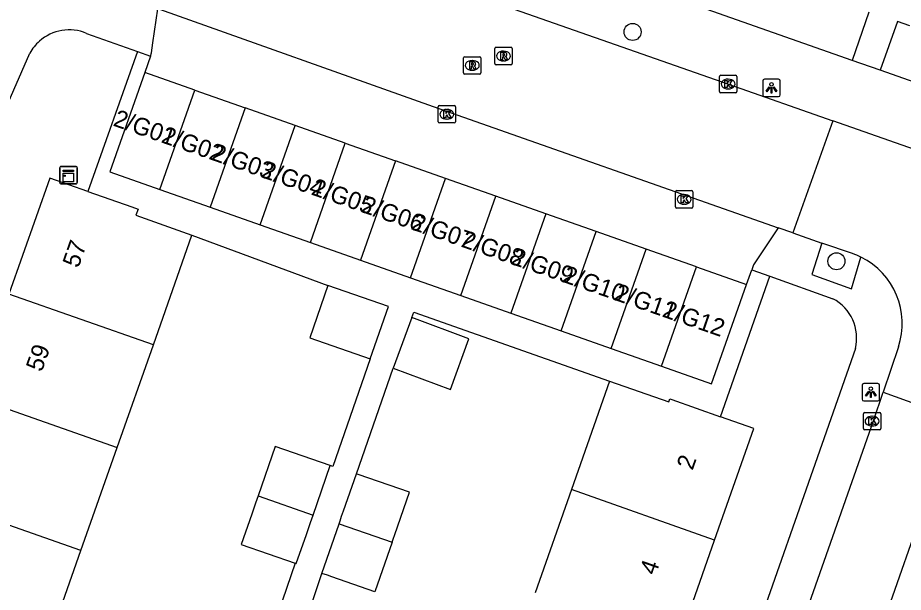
# Model space of a CAD drawing. Extents: x 163268 to 164360, y 381529 to 382285.
# Drawn here: x 163679.2 to 163730.1, y 381780.9 to 381813.9 of the extents above; entities that cross this region are included whole.
import ezdxf

# ---------------------------------------------------------------- set-up
doc = ezdxf.new("R2010")
doc.units = 0
for name, color, linetype in [('IMGEO_Boom', 7, 'Continuous'), ('IMGEO_Kast', 7, 'Continuous'), ('IMGEO_Kolk', 7, 'Continuous'), ('IMGEO_Lichtpunt', 7, 'Continuous'), ('IMGEO_Pand', 7, 'Continuous'), ('IMGEO_Pand_nummerreeks', 7, 'Continuous'), ('IMGEO_Rijbaan_lokaal_open', 7, 'Continuous'), ('IMGEO_Rioolput', 7, 'Continuous'), ('IMGEO_Voetpad_open', 7, 'Continuous')]:
    doc.layers.add(name, color=color, linetype=linetype)

msp = doc.modelspace()

# ---------------------------------------------------------------- linework, layer by layer
at = {"layer": 'IMGEO_Boom'}
for centre in [(163714.53, 381813.112), (163726.256, 381799.927)]:
    msp.add_circle(centre, 0.489, dxfattribs=at)
at = {"layer": 'IMGEO_Kast'}
for p, q in [((163681.652, 381805.379), (163682.493, 381805.379)), ((163682.493, 381805.379), (163681.652, 381805.379)), ((163681.577, 381804.454), (163681.577, 381805.295)), ((163681.577, 381805.295), (163681.577, 381804.454)), ((163682.577, 381805.304), (163682.577, 381804.463)), ((163682.577, 381804.463), (163682.577, 381805.304)), ((163682.502, 381804.379), (163681.661, 381804.379)), ((163681.661, 381804.379), (163682.502, 381804.379))]:
    msp.add_line(p, q, dxfattribs=at)
for points in [[(163681.772, 381805.169), (163682.372, 381805.169), (163682.372, 381805.084), (163681.772, 381805.084), (163681.772, 381805.169)], [(163681.772, 381804.994), (163682.372, 381804.994), (163682.372, 381804.505), (163681.772, 381804.505), (163681.772, 381804.994)]]:
    msp.add_lwpolyline(points, dxfattribs=at)
msp.add_circle((163681.856, 381804.843), 0.0377, dxfattribs=at)
for centre, start, end in [((163681.655, 381805.301), 92.4484, 184.2845), ((163681.655, 381805.301), 92.4484, 184.2845), ((163682.499, 381805.301), 2.4484, 94.2845), ((163682.499, 381805.301), 2.4484, 94.2845), ((163681.655, 381804.457), 182.4484, 274.2845), ((163681.655, 381804.457), 182.4484, 274.2845), ((163682.499, 381804.457), 272.4484, 4.2845), ((163682.499, 381804.457), 272.4484, 4.2845)]:
    msp.add_arc(centre, 0.0779, start, end, dxfattribs=at)
at = {"layer": 'IMGEO_Kolk'}
for p, q in [((163719.522, 381809.693), (163719.522, 381810.545)), ((163719.597, 381810.619), (163720.449, 381810.619)), ((163720.523, 381810.545), (163720.523, 381809.693)), ((163720.01, 381810.399), (163720.035, 381810.399)), ((163720.449, 381809.619), (163719.597, 381809.619)), ((163720.033, 381809.839), (163720.008, 381809.839)), ((163703.341, 381807.953), (163703.341, 381808.805)), ((163703.416, 381808.879), (163704.268, 381808.879)), ((163703.829, 381808.659), (163703.854, 381808.659)), ((163704.342, 381808.805), (163704.342, 381807.953)), ((163703.852, 381808.099), (163703.827, 381808.099)), ((163704.268, 381807.879), (163703.416, 381807.879)), ((163716.996, 381803.062), (163716.996, 381803.914)), ((163717.071, 381803.988), (163717.923, 381803.988)), ((163717.997, 381803.914), (163717.997, 381803.062)), ((163717.484, 381803.768), (163717.509, 381803.768)), ((163717.923, 381802.988), (163717.071, 381802.988)), ((163717.507, 381803.208), (163717.482, 381803.208)), ((163727.803, 381790.312), (163727.803, 381791.164)), ((163727.878, 381791.238), (163728.73, 381791.238)), ((163728.804, 381791.164), (163728.804, 381790.312)), ((163728.291, 381791.018), (163728.316, 381791.018)), ((163728.73, 381790.238), (163727.878, 381790.238)), ((163728.314, 381790.458), (163728.289, 381790.458))]:
    msp.add_line(p, q, dxfattribs=at)
for points in [[(163719.522, 381809.693), (163719.522, 381810.545)], [(163719.597, 381810.619), (163720.449, 381810.619)], [(163720.523, 381810.545), (163720.523, 381809.693)], [(163719.843, 381810.319), (163719.966, 381810.319), (163719.966, 381810.168), (163720.096, 381810.319), (163720.26, 381810.319), (163720.114, 381810.168), (163720.267, 381809.919), (163720.115, 381809.919), (163720.03, 381810.083), (163719.966, 381810.016), (163719.966, 381809.919), (163719.843, 381809.919), (163719.843, 381810.319)], [(163720.449, 381809.619), (163719.597, 381809.619)], [(163703.341, 381807.953), (163703.341, 381808.805)], [(163703.416, 381808.879), (163704.268, 381808.879)], [(163703.662, 381808.579), (163703.785, 381808.579), (163703.785, 381808.428), (163703.915, 381808.579), (163704.079, 381808.579), (163703.933, 381808.428), (163704.086, 381808.179), (163703.934, 381808.179), (163703.849, 381808.343), (163703.785, 381808.276), (163703.785, 381808.179), (163703.662, 381808.179), (163703.662, 381808.579)], [(163704.342, 381808.805), (163704.342, 381807.953)], [(163704.268, 381807.879), (163703.416, 381807.879)], [(163716.996, 381803.062), (163716.996, 381803.914)], [(163717.071, 381803.988), (163717.923, 381803.988)], [(163717.997, 381803.914), (163717.997, 381803.062)], [(163717.317, 381803.688), (163717.44, 381803.688), (163717.44, 381803.537), (163717.57, 381803.688), (163717.734, 381803.688), (163717.588, 381803.537), (163717.741, 381803.288), (163717.589, 381803.288), (163717.504, 381803.452), (163717.44, 381803.385), (163717.44, 381803.288), (163717.317, 381803.288), (163717.317, 381803.688)], [(163717.923, 381802.988), (163717.071, 381802.988)], [(163727.803, 381790.312), (163727.803, 381791.164)], [(163727.878, 381791.238), (163728.73, 381791.238)], [(163728.804, 381791.164), (163728.804, 381790.312)], [(163728.124, 381790.938), (163728.247, 381790.938), (163728.247, 381790.787), (163728.377, 381790.938), (163728.541, 381790.938), (163728.395, 381790.787), (163728.548, 381790.538), (163728.396, 381790.538), (163728.311, 381790.702), (163728.247, 381790.635), (163728.247, 381790.538), (163728.124, 381790.538), (163728.124, 381790.938)], [(163728.73, 381790.238), (163727.878, 381790.238)]]:
    msp.add_lwpolyline(points, dxfattribs=at)
for centre, start, end in [((163719.599, 381810.543), 91.552, 178.448), ((163719.599, 381810.543), 91.552, 178.448), ((163720.447, 381810.543), 1.552, 88.448), ((163720.447, 381810.543), 1.552, 88.448), ((163719.599, 381809.695), 181.552, 268.448), ((163719.599, 381809.695), 181.552, 268.448), ((163720.447, 381809.695), 271.552, 358.448), ((163720.447, 381809.695), 271.552, 358.448), ((163703.418, 381808.803), 91.552, 178.448), ((163703.418, 381808.803), 91.552, 178.448), ((163704.266, 381808.803), 1.552, 88.448), ((163704.266, 381808.803), 1.552, 88.448), ((163703.418, 381807.955), 181.552, 268.448), ((163703.418, 381807.955), 181.552, 268.448), ((163704.266, 381807.955), 271.552, 358.448), ((163704.266, 381807.955), 271.552, 358.448), ((163717.073, 381803.912), 91.552, 178.448), ((163717.073, 381803.912), 91.552, 178.448), ((163717.921, 381803.912), 1.552, 88.448), ((163717.921, 381803.912), 1.552, 88.448), ((163717.073, 381803.064), 181.552, 268.448), ((163717.073, 381803.064), 181.552, 268.448), ((163717.921, 381803.064), 271.552, 358.448), ((163717.921, 381803.064), 271.552, 358.448), ((163727.88, 381791.162), 91.552, 178.448), ((163727.88, 381791.162), 91.552, 178.448), ((163728.728, 381791.162), 1.552, 88.448), ((163728.728, 381791.162), 1.552, 88.448), ((163727.88, 381790.314), 181.552, 268.448), ((163727.88, 381790.314), 181.552, 268.448), ((163728.728, 381790.314), 271.552, 358.448), ((163728.728, 381790.314), 271.552, 358.448)]:
    msp.add_arc(centre, 0.0765, start, end, dxfattribs=at)
for centre, major_axis, ratio, start_param, end_param in [((163720.009, 381810.119), (-0.387, 0.002), 0.722429, 4.712389, 7.853982), ((163720.034, 381810.119), (-0.39, 0.002), 0.717154, 1.570796, 4.712389), ((163703.828, 381808.379), (-0.387, 0.002), 0.722429, 4.712389, 7.853982), ((163703.853, 381808.379), (-0.39, 0.002), 0.717154, 1.570796, 4.712389), ((163717.483, 381803.488), (-0.387, 0.002), 0.722429, 4.712389, 7.853982), ((163717.508, 381803.488), (-0.39, 0.002), 0.717154, 1.570796, 4.712389), ((163728.29, 381790.738), (-0.387, 0.002), 0.722429, 4.712389, 7.853982), ((163728.315, 381790.738), (-0.39, 0.002), 0.717154, 1.570796, 4.712389)]:
    msp.add_ellipse(centre, major_axis=major_axis, ratio=ratio, start_param=start_param, end_param=end_param, dxfattribs=at)
at = {"layer": 'IMGEO_Lichtpunt'}
for p, q in [((163722.02, 381810.301), (163722.02, 381809.494)), ((163722.02, 381810.301), (163722.02, 381809.494)), ((163722.922, 381810.396), (163722.114, 381810.396)), ((163722.922, 381810.396), (163722.114, 381810.396)), ((163723.016, 381809.494), (163723.016, 381810.301)), ((163723.016, 381809.494), (163723.016, 381810.301)), ((163722.114, 381809.4), (163722.922, 381809.4)), ((163722.114, 381809.4), (163722.922, 381809.4)), ((163727.735, 381792.805), (163727.735, 381791.998)), ((163727.735, 381792.805), (163727.735, 381791.998)), ((163728.637, 381792.9), (163727.829, 381792.9)), ((163728.637, 381792.9), (163727.829, 381792.9)), ((163728.731, 381791.998), (163728.731, 381792.805)), ((163728.731, 381791.998), (163728.731, 381792.805)), ((163727.829, 381791.904), (163728.637, 381791.904)), ((163727.829, 381791.904), (163728.637, 381791.904))]:
    msp.add_line(p, q, dxfattribs=at)
for points in [[(163722.394, 381809.965), (163722.433, 381809.937), (163722.245, 381809.675), (163722.207, 381809.702), (163722.394, 381809.965)], [(163722.606, 381809.937), (163722.644, 381809.964), (163722.831, 381809.702), (163722.792, 381809.674), (163722.606, 381809.937)], [(163722.496, 381809.917), (163722.543, 381809.917), (163722.543, 381809.595), (163722.496, 381809.595), (163722.496, 381809.917)], [(163728.109, 381792.469), (163728.148, 381792.441), (163727.96, 381792.179), (163727.922, 381792.206), (163728.109, 381792.469)], [(163728.211, 381792.421), (163728.258, 381792.421), (163728.258, 381792.099), (163728.211, 381792.099), (163728.211, 381792.421)], [(163728.321, 381792.441), (163728.359, 381792.468), (163728.546, 381792.206), (163728.507, 381792.178), (163728.321, 381792.441)]]:
    msp.add_lwpolyline(points, dxfattribs=at)
for centre in [(163722.519, 381810.099), (163728.234, 381792.603)]:
    msp.add_circle(centre, 0.0994, dxfattribs=at)
for centre, start, end in [((163722.114, 381810.301), 90, 180), ((163722.114, 381810.301), 90, 180), ((163722.922, 381810.301), 0, 90), ((163722.922, 381810.301), 0, 90), ((163722.114, 381809.494), 180, 270), ((163722.114, 381809.494), 180, 270), ((163722.922, 381809.494), 270, 0), ((163722.922, 381809.494), 270, 360), ((163727.829, 381792.805), 90, 180), ((163727.829, 381792.805), 90, 180), ((163728.637, 381792.805), 0, 90), ((163728.637, 381792.805), 0, 90), ((163727.829, 381791.998), 180, 270), ((163727.829, 381791.998), 180, 270), ((163728.637, 381791.998), 270, 0), ((163728.637, 381791.998), 270, 360)]:
    msp.add_arc(centre, 0.0946, start, end, dxfattribs=at)
at = {"layer": 'IMGEO_Pand'}
for points in [[(163686.459, 381810.779), (163684.448, 381805.066), (163687.333, 381804.05)], [(163689.345, 381809.763), (163686.459, 381810.779)], [(163687.333, 381804.05), (163689.345, 381809.763)], [(163689.345, 381809.763), (163692.23, 381808.748)], [(163692.23, 381808.748), (163690.219, 381803.034)], [(163695.115, 381807.732), (163692.23, 381808.748)], [(163693.104, 381802.019), (163695.115, 381807.732)], [(163698, 381806.716), (163695.115, 381807.732)], [(163695.989, 381801.003), (163698, 381806.716)], [(163698, 381806.716), (163700.886, 381805.701)], [(163700.886, 381805.701), (163698.874, 381799.987)], [(163703.771, 381804.685), (163700.886, 381805.701)], [(163683.186, 381803.942), (163681.001, 381804.712), (163678.652, 381798.043)], [(163701.76, 381798.972), (163703.771, 381804.685)], [(163706.656, 381803.669), (163703.771, 381804.685)], [(163683.186, 381803.942), (163685.717, 381803.051), (163686.08, 381802.923), (163685.957, 381802.573), (163689.18, 381801.438)], [(163687.333, 381804.05), (163690.219, 381803.034)], [(163704.645, 381797.956), (163706.656, 381803.669)], [(163709.541, 381802.654), (163706.656, 381803.669)], [(163690.219, 381803.034), (163693.104, 381802.019)], [(163709.541, 381802.654), (163707.53, 381796.94)], [(163712.427, 381801.638), (163709.541, 381802.654)], [(163693.104, 381802.019), (163695.989, 381801.003)], [(163686.959, 381795.132), (163689.18, 381801.438)], [(163710.415, 381795.924), (163712.427, 381801.638)], [(163715.312, 381800.622), (163712.427, 381801.638)], [(163695.989, 381801.003), (163698.874, 381799.987)], [(163713.3, 381794.908), (163715.312, 381800.622)], [(163718.197, 381799.606), (163715.312, 381800.622)], [(163698.874, 381799.987), (163701.76, 381798.972)], [(163716.186, 381793.893), (163718.197, 381799.606)], [(163718.197, 381799.606), (163721.082, 381798.591)], [(163701.76, 381798.972), (163704.645, 381797.956)], [(163697.003, 381798.534), (163695.961, 381795.52), (163699.434, 381794.32)], [(163699.434, 381794.32), (163700.476, 381797.334), (163697.003, 381798.534)], [(163716.186, 381793.893), (163719.071, 381792.877), (163721.082, 381798.591)], [(163686.959, 381795.132), (163678.652, 381798.043)], [(163704.645, 381797.956), (163707.53, 381796.94)], [(163707.53, 381796.94), (163710.415, 381795.924)], [(163701.825, 381796.689), (163700.753, 381793.774)], [(163700.753, 381793.774), (163704.043, 381792.564), (163705.115, 381795.479), (163701.825, 381796.689)], [(163710.415, 381795.924), (163713.3, 381794.908)], [(163684.876, 381789.218), (163686.959, 381795.132)], [(163713.3, 381794.908), (163716.186, 381793.893)], [(163713.208, 381793.042), (163711.009, 381786.801)], [(163713.208, 381793.042), (163716.608, 381791.845), (163716.668, 381792.016), (163716.791, 381791.973), (163719.576, 381790.993)], [(163676.569, 381792.13), (163684.876, 381789.218)], [(163719.249, 381783.902), (163721.507, 381790.314), (163719.576, 381790.993)], [(163682.793, 381783.305), (163684.876, 381789.218)], [(163697.139, 381788.189), (163693.974, 381789.288), (163692.983, 381786.435)], [(163696.148, 381785.337), (163697.139, 381788.189)], [(163697.64, 381784.841), (163697.698, 381785.01), (163697.788, 381785.267), (163697.899, 381785.587), (163698.637, 381787.711)], [(163700.691, 381783.782), (163700.75, 381783.951), (163700.841, 381784.213), (163701.688, 381786.651), (163698.736, 381787.677), (163698.637, 381787.711)], [(163711.009, 381786.801), (163708.919, 381780.869)], [(163719.249, 381783.902), (163711.009, 381786.801)], [(163682.793, 381783.305), (163674.486, 381786.216)], [(163692.983, 381786.435), (163692.838, 381786.018), (163692.619, 381785.386), (163692.014, 381783.644), (163695.11, 381782.57)], [(163692.983, 381786.435), (163696.148, 381785.337)], [(163695.11, 381782.57), (163695.179, 381782.546), (163695.761, 381784.222), (163696.003, 381784.919), (163696.148, 381785.337)], [(163696.648, 381781.987), (163697.64, 381784.841)], [(163697.64, 381784.841), (163700.691, 381783.782)], [(163700.691, 381783.782), (163699.7, 381780.928), (163697.218, 381781.79), (163696.979, 381781.873), (163696.648, 381781.987)], [(163717.161, 381777.97), (163719.249, 381783.902)], [(163680.71, 381777.391), (163682.793, 381783.305)]]:
    msp.add_lwpolyline(points, dxfattribs=at)
at = {"layer": 'IMGEO_Rijbaan_lokaal_open'}
for points in [[(163685.076, 381822.394), (163704.639, 381815.509), (163720.044, 381810.112), (163726.041, 381807.998)], [(163687.218, 381814.444), (163687.304, 381814.414), (163703.06, 381808.819), (163722.904, 381801.849)], [(163726.041, 381807.998), (163723.746, 381801.558)], [(163758.246, 381796.703), (163740.853, 381802.813), (163726.041, 381807.998)], [(163723.746, 381801.558), (163722.904, 381801.849)], [(163723.746, 381801.558), (163725.421, 381800.978)], [(163727.182, 381800.368), (163725.421, 381800.978)], [(163729.821, 381795.001), (163728.949, 381792.401)], [(163708.144, 381732.996), (163708.709, 381734.601), (163714.691, 381751.607), (163721.738, 381771.833), (163728.396, 381790.753), (163728.949, 381792.401)], [(163728.949, 381792.401), (163733.076, 381790.916)], [(163733.076, 381790.916), (163732.482, 381789.267), (163727.899, 381776.195)]]:
    msp.add_lwpolyline(points, dxfattribs=at)
for centre, radius, start, end in [((163725.727, 381796.191), 4.423, 63.9837, 70.7934), ((163725.791, 381796.352), 4.25, 341.4655, 63.8105)]:
    msp.add_arc(centre, radius, start, end, dxfattribs=at)
at = {"layer": 'IMGEO_Rioolput'}
for p, q in [((163706.601, 381811.303), (163706.601, 381812.155)), ((163706.676, 381812.229), (163707.528, 381812.229)), ((163707.089, 381812.009), (163707.114, 381812.009)), ((163707.602, 381812.155), (163707.602, 381811.303)), ((163704.804, 381810.764), (163704.804, 381811.616)), ((163704.879, 381811.69), (163705.731, 381811.69)), ((163705.805, 381811.616), (163705.805, 381810.764)), ((163705.292, 381811.47), (163705.317, 381811.47)), ((163707.528, 381811.229), (163706.676, 381811.229)), ((163707.112, 381811.449), (163707.087, 381811.449)), ((163705.731, 381810.69), (163704.879, 381810.69)), ((163705.315, 381810.91), (163705.29, 381810.91))]:
    msp.add_line(p, q, dxfattribs=at)
for points in [[(163706.601, 381811.303), (163706.601, 381812.155)], [(163706.676, 381812.229), (163707.528, 381812.229)], [(163707.602, 381812.155), (163707.602, 381811.303)], [(163704.804, 381810.764), (163704.804, 381811.616)], [(163704.879, 381811.69), (163705.731, 381811.69)], [(163705.805, 381811.616), (163705.805, 381810.764)], [(163707.19, 381811.927), (163706.938, 381811.929), (163706.938, 381811.529)], [(163706.938, 381811.529), (163707.062, 381811.529), (163707.062, 381811.691), (163707.073, 381811.691)], [(163707.116, 381811.848), (163707.062, 381811.848), (163707.062, 381811.767)], [(163707.062, 381811.767), (163707.114, 381811.767)], [(163707.12, 381811.662), (163707.191, 381811.529), (163707.331, 381811.529), (163707.266, 381811.655)], [(163705.393, 381811.388), (163705.141, 381811.39), (163705.141, 381810.99)], [(163705.141, 381810.99), (163705.265, 381810.99), (163705.265, 381811.152), (163705.276, 381811.152)], [(163705.319, 381811.309), (163705.265, 381811.309), (163705.265, 381811.228)], [(163705.265, 381811.228), (163705.317, 381811.228)], [(163705.323, 381811.123), (163705.394, 381810.99), (163705.534, 381810.99), (163705.469, 381811.116)], [(163707.528, 381811.229), (163706.676, 381811.229)], [(163705.731, 381810.69), (163704.879, 381810.69)]]:
    msp.add_lwpolyline(points, dxfattribs=at)
for centre, radius, start, end in [((163706.678, 381812.153), 0.0765, 91.552, 178.448), ((163706.678, 381812.153), 0.0765, 91.552, 178.448), ((163707.526, 381812.153), 0.0765, 1.552, 88.448), ((163707.526, 381812.153), 0.0765, 1.552, 88.448), ((163704.881, 381811.614), 0.0765, 91.552, 178.448), ((163704.881, 381811.614), 0.0765, 91.552, 178.448), ((163705.729, 381811.614), 0.0765, 1.552, 88.448), ((163705.729, 381811.614), 0.0765, 1.552, 88.448), ((163707.072, 381811.638), 0.0533, 26.0293, 88.6989), ((163707.098, 381811.956), 0.19, 274.7715, 282.9687), ((163707.122, 381811.752), 0.0964, 77.0061, 93.1865), ((163707.136, 381811.809), 0.0378, 276.6634, 79.6772), ((163707.189, 381811.817), 0.109, 350.3612, 89.416), ((163707.187, 381811.817), 0.112, 277.5842, 350.9817), ((163707.171, 381811.602), 0.108, 29.5134, 73.7905), ((163705.275, 381811.099), 0.0533, 26.0293, 88.6989), ((163705.301, 381811.417), 0.19, 274.7715, 282.9687), ((163705.325, 381811.213), 0.0964, 77.0061, 93.1865), ((163705.339, 381811.27), 0.0378, 276.6634, 79.6772), ((163705.392, 381811.278), 0.109, 350.3612, 89.416), ((163705.39, 381811.278), 0.112, 277.5842, 350.9817), ((163705.374, 381811.063), 0.108, 29.5134, 73.7905), ((163706.678, 381811.305), 0.0765, 181.552, 268.448), ((163706.678, 381811.305), 0.0765, 181.552, 268.448), ((163707.526, 381811.305), 0.0765, 271.552, 358.448), ((163707.526, 381811.305), 0.0765, 271.552, 358.448), ((163704.881, 381810.766), 0.0765, 181.552, 268.448), ((163704.881, 381810.766), 0.0765, 181.552, 268.448), ((163705.729, 381810.766), 0.0765, 271.552, 358.448), ((163705.729, 381810.766), 0.0765, 271.552, 358.448)]:
    msp.add_arc(centre, radius, start, end, dxfattribs=at)
for centre, major_axis, ratio, start_param, end_param in [((163707.088, 381811.729), (-0.387, 0.002), 0.722429, 4.712389, 7.853982), ((163707.113, 381811.729), (-0.39, 0.002), 0.717154, 1.570796, 4.712389), ((163705.291, 381811.19), (-0.387, 0.002), 0.722429, 4.712389, 7.853982), ((163705.316, 381811.19), (-0.39, 0.002), 0.717154, 1.570796, 4.712389)]:
    msp.add_ellipse(centre, major_axis=major_axis, ratio=ratio, start_param=start_param, end_param=end_param, dxfattribs=at)
at = {"layer": 'IMGEO_Voetpad_open'}
for points in [[(163727.155, 381811.48), (163687.737, 381825.353)], [(163686.787, 381811.726), (163686.854, 381811.92), (163686.921, 381812.493), (163687.218, 381814.444)], [(163728.128, 381814.246), (163727.155, 381811.48)], [(163730.484, 381813.465), (163729.761, 381813.719), (163728.773, 381810.911)], [(163683.111, 381813.033), (163686.047, 381811.989)], [(163686.047, 381811.989), (163683.186, 381803.942)], [(163686.047, 381811.989), (163686.787, 381811.726)], [(163653.198, 381750), (163653.323, 381751.193), (163679.851, 381811.893)], [(163686.787, 381811.726), (163686.459, 381810.779)], [(163728.773, 381810.911), (163727.155, 381811.48)], [(163787.244, 381790.333), (163728.773, 381810.911)], [(163722.904, 381801.849), (163721.492, 381799.731), (163721.386, 381799.437)], [(163689.18, 381801.438), (163697.003, 381798.534)], [(163725.421, 381800.978), (163724.833, 381799.167), (163727.129, 381798.351), (163727.667, 381800.166)], [(163721.082, 381798.591), (163721.386, 381799.437)], [(163721.386, 381799.437), (163722.417, 381799.071)], [(163719.576, 381790.993), (163722.417, 381799.071)], [(163722.417, 381799.071), (163726.054, 381797.778)], [(163701.825, 381796.689), (163701.942, 381797.008), (163713.208, 381793.042)], [(163727.346, 381794.905), (163711.594, 381750), (163705.54, 381732.742)], [(163699.434, 381794.32), (163697.285, 381788.135), (163697.139, 381788.189)], [(163698.637, 381787.711), (163700.753, 381793.774)], [(163695.11, 381782.57), (163692.927, 381776.181)], [(163694.549, 381775.627), (163696.648, 381781.987)]]:
    msp.add_lwpolyline(points, dxfattribs=at)
for centre, radius, start, end in [((163682.119, 381810.637), 2.593, 67.5074, 131.4104), ((163682.13, 381810.63), 2.606, 131.4888, 151.0092), ((163724.849, 381795.509), 2.569, 346.3945, 62.0328)]:
    msp.add_arc(centre, radius, start, end, dxfattribs=at)

# ---------------------------------------------------------------- texts
at = {"layer": 'IMGEO_Pand_nummerreeks'}
for s, rotation, p in [('2/G01', 340.8411, (163684.594, 381807.737)), ('2/G02', 340.8411, (163687.357, 381806.777)), ('2/G03', 340.8411, (163690.237, 381805.777)), ('2/G04', 340.8411, (163693.11, 381804.778)), ('2/G05', 340.8411, (163695.983, 381803.78)), ('2/G06', 340.8411, (163698.857, 381802.782)), ('2/G07', 340.8411, (163701.73, 381801.784)), ('2/G08', 340.8411, (163704.606, 381800.784)), ('57', 70.5941, (163682.644, 381799.503)), ('2/G09', 340.8411, (163707.473, 381799.788)), ('2/G10', 340.8411, (163710.439, 381798.758)), ('2/G11', 340.8411, (163713.413, 381797.724)), ('2/G12', 340.8411, (163716.176, 381796.764)), ('59', 70.5954, (163680.538, 381793.526)), ('2', 70.6056, (163717.975, 381787.87)), ('4', 70.6035, (163715.849, 381781.832))]:
    msp.add_text(s, height=1, rotation=rotation, dxfattribs=at).set_placement(p)

doc.saveas('drawing.dxf')
